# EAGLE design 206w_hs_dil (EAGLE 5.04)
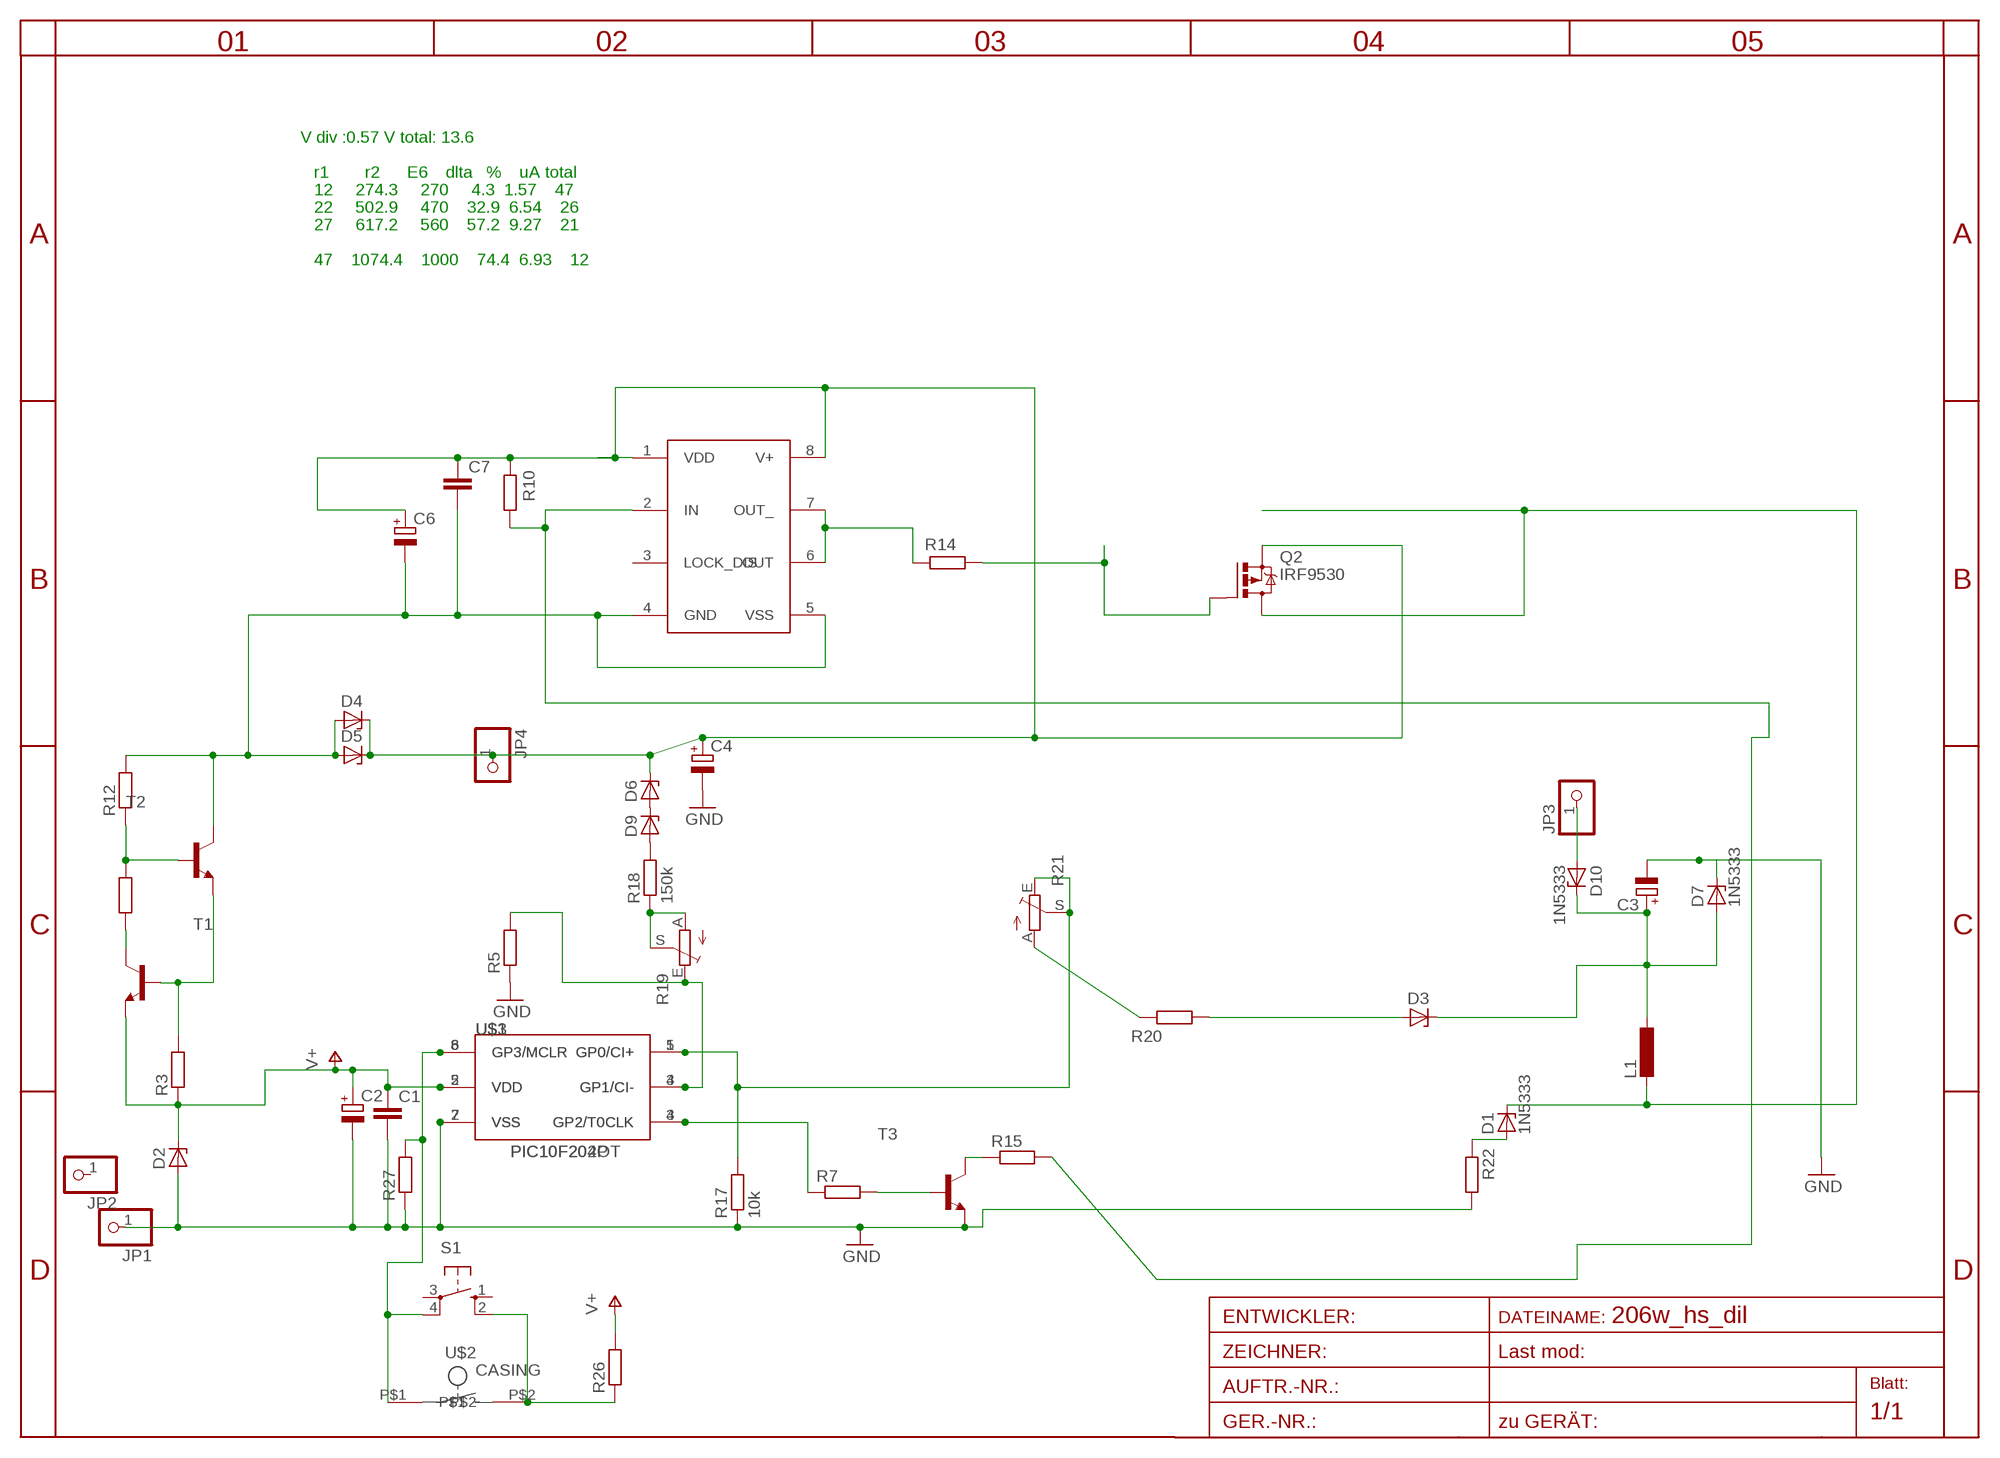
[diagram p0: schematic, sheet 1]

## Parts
C1  C-EUC1206  [C1206]
C2  CPOL-EUSANYO_SMD_E12  [SANYO-OSCON_SMD_E12]
C3  CPOL-EUE5-8.5  [E5-8,5]
C4  CPOL-EUE5-8.5  [E5-8,5]
C6  CPOL-EUSANYO_SMD_E12  [SANYO-OSCON_SMD_E12]
C7  C-EUC1206  [C1206]
D1  1N5333  [C1702-15]
D2  ZENER-DIODESOT23  [SOT23]
D3  ZENER-DIODESMB  [SMB]
D4  ZENER-DIODESMB  [SMB]
D5  ZENER-DIODESMB  [SMB]
D6  ZENER-DIODESMB  [SMB]
D7  1N5333  [C1702-15]
D9  ZENER-DIODESMB  [SMB]
D10  1N5333  [C1702-15]
IC3  TC4432X  [SO-08]
JP1  PINHD-1X1  [1X01]
JP2  PINHD-1X1  [1X01]
JP3  PINHD-1X1  [1X01]
JP4  PINHD-1X1  [1X01]
L1  L-EU2200-15.24  [2200-15.24]
Q2  IRF9530  [TO220BV]
R3  R-EU_R0805  [R0805]
R5  R-EU_R0805  [R0805]
R7  R-EU_R0805  [R0805]
R10  R-EU_R0805  [R0805]
R12  R-EU_R0805  [R0805]
R14  R-EU_0204/2V  [0204V]
R15  R-EU_R0805  [R0805]
R17  10k  R-EU_R0805  [R0805]
R18  150k  R-EU_R1206  [R1206]
R19  TRIM_EU-CA6V  [CA6V]
R20  R-EU_R0805  [R0805]
R21  TRIM_EU-CA6V  [CA6V]
R22  R-EU_0309/12  [0309/12]
R24  R-EU_R1206  [R1206]
R26  R-EU_R0805  [R0805]
R27  R-EU_R0805  [R0805]
S1  10-XX  [B3F-10XX]
T1  BC846BLT1-NPN-SOT23-BEC  [SOT23-BEC]
T2  BC846BLT1-NPN-SOT23-BEC  [SOT23-BEC]
T3  BC846BLT1-NPN-SOT23-BEC  [SOT23-BEC]
U$1  PIC10F202OT  [SOT23-6]
U$2  CASING  [CASING]
U$3  PIC10F204P  [DIL8]

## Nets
BB: IC3.2(IN) R10.1 R15.2
EXIT: D10.A JP3.1
GND: C1.2 C2.- C3.- C4.- D2.1(A) D7.C JP1.1 R5.1 R17.1 R22.2 R27.1 T3.E U$1.2(VSS) U$3.7(VSS)
HOTSPOT: D1.C L1.2 Q2.D
N$1: D3.A R20.2
N$2: R15.1 T3.C
N$3: R5.2 R19.E U$1.3(GP1/CI-) U$3.4(GP1/CI-)
N$4: D9.A R18.2
N$5: R7.2 T3.B
N$6: C6.- C7.2 D4.A D5.A IC3.4(GND) IC3.5(VSS) R12.2 T2.C
N$7: R27.2 S1.4(P1) U$1.6(GP3/MCLR) U$2.P$1 U$3.8(GP3/MCLR)
N$8: D1.A R22.1
N$9: R7.1 U$1.4(GP2/T0CLK) U$3.3(GP2/T0CLK)
N$10: Q2.G R14.1
N$11: IC3.6(OUT) IC3.7(OUT_) R14.2
N$12: R3.2 T1.B T2.E
N$13: R18.1 R19.A R19.S
N$14: R17.2 R21.E R21.S U$1.1(GP0/CI+) U$3.5(GP0/CI+)
N$17: R26.1 S1.2(S1) U$2.P$2
N$19: R24.1 T1.C
N$22: R12.1 R24.2 T2.B
N$23: D6.A D9.C
N$25: R20.1 R21.A
V60: C4.+ C6.+ C7.1 D4.C D5.C D6.C IC3.1(VDD) IC3.8(V+) JP4.1 Q2.S R10.2
V+: C1.1 C2.+ D2.3(C) R3.1 R26.2 T1.E U$1.5(VDD) U$3.2(VDD)
VOUT: C3.+ D3.C D7.A D10.C L1.1
Unconnected: IC3.3(LOCK_DIS) JP2.1 S1.1(S) S1.3(P)

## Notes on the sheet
- V div :0.57 V total: 13.6
- r1        r2      E6    dlta   %    uA total
- 12     274.3     270     4.3  1.57    47
- 22     502.9     470    32.9  6.54    26
- 27     617.2     560    57.2  9.27    21
- 47    1074.4    1000    74.4  6.93    12

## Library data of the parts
C1 C7 = rcl:C-EU: CAPACITOR, European symbol
C2-C4 C6 = rcl:CPOL-EU: POLARIZED CAPACITOR, European symbol
D1 D7 D10 = diode-1:1N5333: Z DIODE
D2-D6 D9 = diode-1:ZENER-DIODE: Z-Diode
IC3 = microchip:TC4432
JP1-JP4 = pinhead:PINHD-1X1: PIN HEADER
L1 = rcl:L-EU: INDUCTOR, European symbol
Q2 = transistor-power:IRF9530: P-CHANNEL HEXFET POWER-MOS-FET Source: http://www.irf.com/product-info/datasheets/data/irf9530.pdf
R3 R5 R10 R12 R14 R15 R20 R24 R26 R27 = rcl:R-EU_: RESISTOR, European symbol
R7 R17 R18 R22 = rcl-2:R-EU_: RESISTOR, European symbol
R19 R21 = pot:TRIM_EU-: POTENTIOMETER
S1 = switch-omron:10-XX: OMRON SWITCH
T1-T3 = transistor-neu-to92:*-NPN-: NPN Transistror
U$1 U$3 = microchip-5:PIC10F2*: uPC nW 0,25/0,5k Program Flash memory Comparator
U$2 = button:CASING

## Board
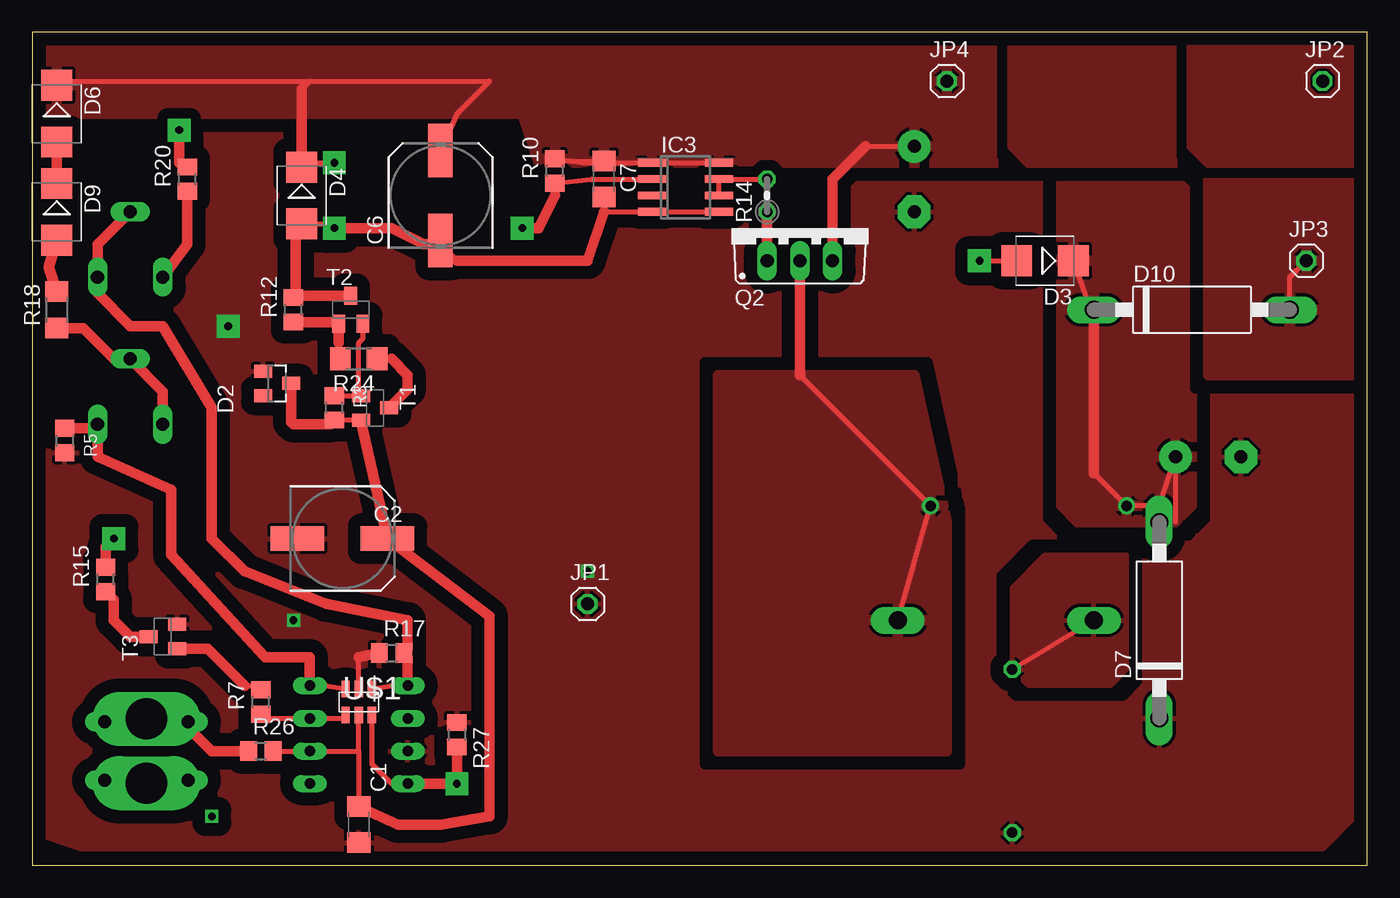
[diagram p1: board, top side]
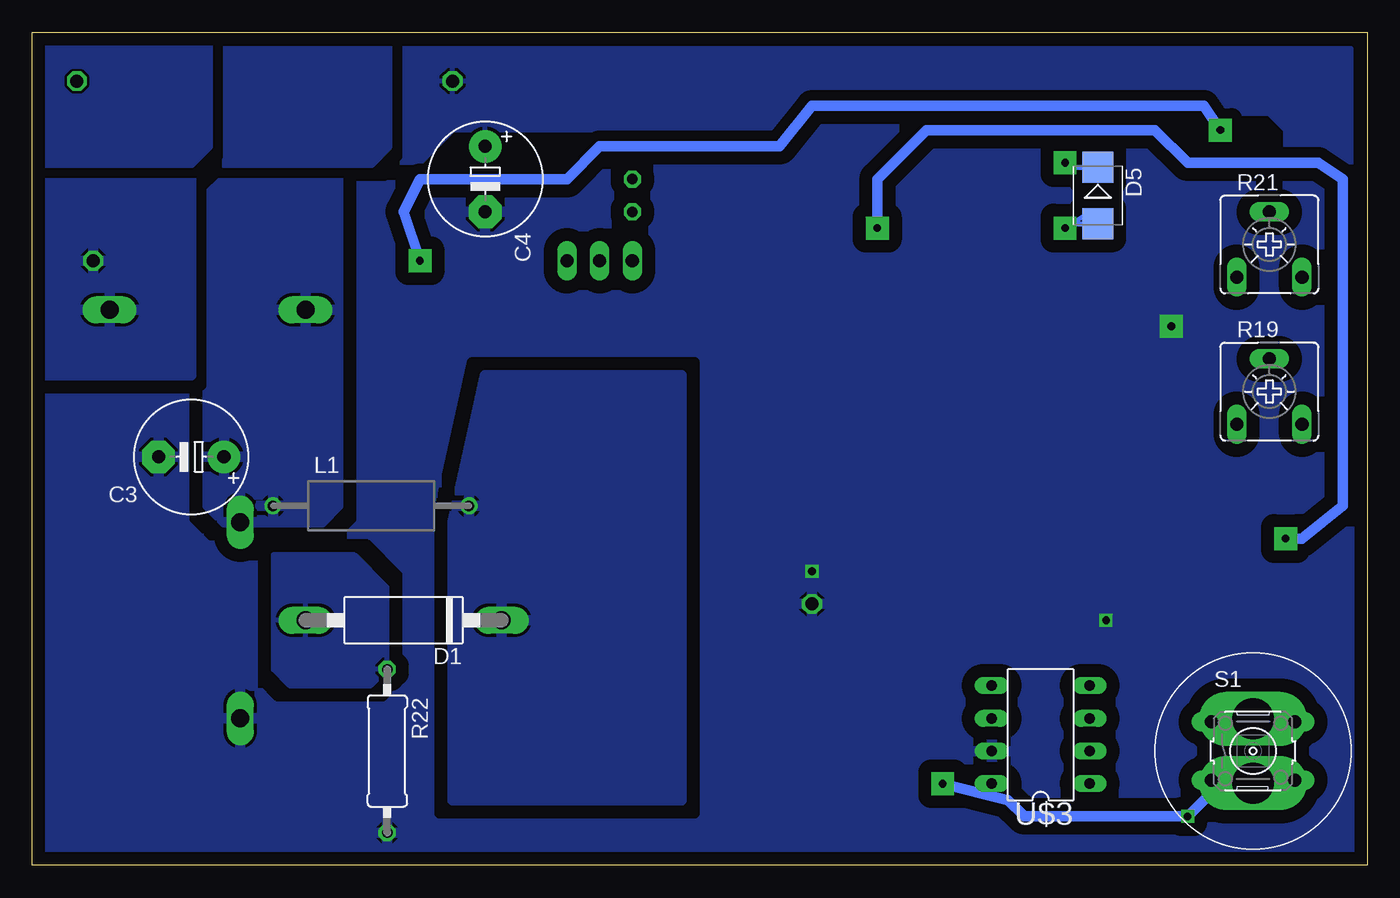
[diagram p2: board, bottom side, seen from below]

Size 103.81 x 64.76 mm. Coordinates in mm from the lower left corner, seen from the top.
Outline: 0,0 103.81,0 103.81,64.76 0,64.76 0,0
Copper layers (1*16): Top 0.035mm / dielectric 1.5mm / Bottom 0.035mm
Design rules "default": minimum track width 10mil, minimum drill 24mil, track to track 8mil, track to pad 8mil, pad to pad 8mil, via to via 8mil, smd to smd 8mil, copper to edge 40mil, drill to drill 8mil, minimum pad ring 10mil, minimum via ring 8mil, stop-mask expansion 4mil, vias tented up to drill 0mil, thermal gap 10mil

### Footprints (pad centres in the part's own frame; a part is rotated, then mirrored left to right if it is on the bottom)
C1206 = smd 1.6 x 1.8: 1 -1.4,0; 2 1.4,0
SANYO-OSCON_SMD_E12 = smd 4.15 x 1.9: + 3.5,0; - -3.5,0
E5-8,5 = drill 1.016 pad 2.54 round: + -2.54,0 | drill 1.016 pad 2.54 octagon: - 2.54,0
C1702-15 = drill 1.397 long: A 7.62,0; C -7.62,0
SOT23 = smd 1 x 1.4: 1 -0.95,-1.1; 2 0.95,-1.1; 3 0,1.1
SMB = smd 2.4 x 2.4: A 2.2,0; C -2.2,0
SO-08 = smd 0.6 x 2.2: 1 -1.905,-2.6; 2 -0.635,-2.6; 3 0.635,-2.6; 4 1.905,-2.6; 5 1.905,2.6; 6 0.635,2.6; 7 -0.635,2.6; 8 -1.905,2.6
1X01 = drill 1.016 octagon: 1 0,0
2200-15.24 = drill 0.8 pad 1.27 round: 1 -7.62,0; 2 7.62,0
TO220BV = drill 1.016 long: D 0,-2.54; G -2.54,-2.54; S 2.54,-2.54
R0805 = smd 1.3 x 1.5: 1 -0.95,0; 2 0.95,0
0204V = drill 0.813 octagon: 1 -1.27,0; 2 1.27,0
R1206 = smd 1.6 x 1.803: 1 -1.422,0; 2 1.422,0
CA6V = drill 1.016 long: A -2.54,-2.54; E 2.54,-2.54; S 0,2.54
0309/12 = drill 0.813 octagon: 1 -6.35,0; 2 6.35,0
B3F-10XX = drill 1.016 long: 1 -3.251,2.261; 2 3.251,2.261; 3 -3.251,-2.261; 4 3.251,-2.261
SOT23-BEC = smd 1 x 1.4: B -0.95,-1.1; C 0,1.1; E 0.95,-1.1
SOT23-6 = smd 0.635 x 1.27: 1 -1.016,-1.016; 2 0,-1.016; 3 1.016,-1.016; 4 1.016,1.016; 5 0,1.016; 6 -1.016,1.016
CASING = drill 3.2 pad 3.81 long: P$1 -2.5,0; P$2 2.5,0
DIL8 = drill 0.813 long: 1 -3.81,-3.81; 2 -1.27,-3.81; 3 1.27,-3.81; 4 3.81,-3.81; 5 3.81,3.81; 6 1.27,3.81; 7 -1.27,3.81; 8 -3.81,3.81

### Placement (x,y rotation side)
C1  25.4,3.17 270 top
C2  24.13,25.4 0 top
C3  91.44,31.75 180 bottom
C4  68.58,53.34 270 bottom
C6  31.75,52.07 90 top
C7  44.45,53.34 270 top
D1  74.93,19.05 180 bottom
D2  19.05,37.47 270 top
D3  78.74,46.99 180 top
D4  20.95,52.07 270 top
D5  20.95,52.07 270 bottom
D6  1.91,58.42 270 top
D7  87.63,19.05 90 top
D9  1.91,50.8 270 top
D10  90.17,43.18 0 top
IC3  50.8,52.7 270 top
JP1  43.18,20.32 0 top
JP2  100.33,60.96 0 top
JP3  99.06,46.99 0 top
JP4  71.12,60.96 0 top
L1  77.47,27.94 0 bottom
Q2  59.69,49.53 0 top
R3  23.5,35.56 90 top
R5  2.54,33.02 90 top
R7  17.78,12.7 90 top
R10  40.64,53.98 90 top
R12  20.32,43.18 90 top
R14  57.15,52.07 90 top
R15  5.71,22.23 90 top
R17  27.94,16.51 0 top
R18  1.91,43.18 90 top
R19  7.62,36.83 0 bottom
R20  12.06,53.34 90 top
R21  7.62,48.26 0 bottom
R22  76.2,8.89 270 bottom
R24  25.4,39.37 180 top
R26  17.78,8.89 0 top
R27  33.02,10.16 270 top
S1  8.89,8.89 0 bottom
T1  26.67,35.56 270 top
T2  24.77,43.18 0 top
T3  10.16,17.78 90 top
U$1  25.4,12.7 180 top
U$2  8.89,8.89 90 bottom
U$3  25.4,10.16 90 bottom

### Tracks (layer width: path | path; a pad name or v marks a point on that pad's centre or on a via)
BB  (via drill 0.6 pad 1.78)
  Top 0.406: IC3.2 43.5,53.34 R10.1 40.64,52.07 | 5.71,24.77 v6.35,25.4
  Top 0.813: 40.64,52.07 39.37,49.53 v38.1,49.53 | R15.2 5.71,24.77
  Bottom 0.813: v6.35,25.4 5.08,25.4 1.91,27.94 1.91,53.34 3.81,54.61 13.97,54.61 16.51,57.15 34.29,57.15 38.1,53.34 v38.1,49.53
EXIT
  Top 0.406: D10.A 97.79,45.72 JP3.1
  pour Top (isolate 0.813, rank 2): 91.44,53.34 102.87,53.34 102.87,38.1 91.44,38.1
  pour Bottom (isolate 0.813, rank 2): 91.44,53.34 102.87,53.34 102.87,38.1 91.44,38.1
GND  (via drill 0.6, 0.6 pad 1.78)
  Top 0.406: U$1.2 25.4,16.19
  Top 0.813: 25.4,16.19 R17.1
  other vias: 15.24,41.91 20.32,19.05 43.18,22.86
  pour Bottom (isolate 1.016, rank 5): 102.87,60.96 102.87,0 90.17,0 1.27,1.27 1.27,53.34 1.27,58.42
  pour Top (isolate 1.016, rank 5): 0,63.5 99.06,63.5 102.87,59.69 102.87,3.81 100.33,1.27 3.81,1.27 0,2.54
HOTSPOT
  Top 0.406: 59.69,38.1 L1.2 D1.C
  Top 0.813: 59.69,38.1 Q2.D
  pour Top (isolate 0.813, rank 3): 53.34,38.1 68.58,38.1 71.12,26.67 71.12,8.89 53.34,8.89
  pour Bottom (isolate 0.813, rank 3): 53.34,38.1 68.58,38.1 71.12,26.67 71.12,5.08 53.34,5.08
N$1  (via drill 0.6 pad 1.78)
  Top 0.406: v73.66,46.99 D3.A | 11.43,54.61 11.74,54.61 R20.2
  Top 0.813: 11.43,54.61 v11.43,57.15
  Bottom 0.813: v73.66,46.99 74.93,50.8 73.66,53.34 62.23,53.34 59.69,55.88 45.72,55.88 43.18,59.05 12.7,59.05 v11.43,57.15
N$2
  Top 0.406: 6.35,20.64 R15.1
  Top 0.813: T3.C 7.62,17.78 6.35,19.05 6.35,20.64
N$3
  Top 0.406: U$1.3 22.86,13.97 U$3.4 | R19.E 4.76,33.97
  Top 0.813: U$3.4 21.59,16.19 18.1,16.19 10.79,24.13 10.79,29.21 5.08,31.75 R19.E | 4.76,33.97 R5.2
N$4
  Top 0.813: D9.A 1.27,46.51 R18.2
N$5
  Top 0.406: 16.51,13.97 17.46,13.97 R7.2
  Top 0.813: T3.B 13.65,16.83 16.51,13.97
N$6  (via drill 0.6 pad 1.78)
  Top 0.406: C7.2 44.45,50.8 IC3.4 IC3.5 | R12.2 20.47,44.28 | 20.47,49.38 D5.A 23.2,49.87 v23.5,49.53 | 33.02,46.99 31.75,48.26 C6.-
  Top 0.813: T2.C 20.47,44.28 20.47,49.38 | 33.02,46.99 43.18,46.99 44.45,50.8 | v23.5,49.53 27.94,49.53 30.48,48.26 31.75,48.26
  Bottom 0.406: 20.32,49.53 21.59,50.8 v23.5,49.53 23.2,49.87 D5.A
N$7  (via drill 0.6, 0.6 pad 1.78)
  Top 0.406: U$1.6 26.42,7.87 27.94,6.35 U$3.8
  Top 0.813: U$3.8 v33.02,6.35 R27.2
  Bottom 0.406: S1.4 11.15,6.63 11.43,6.35 11.39,6.39 U$2.P$1
  Bottom 0.813: v33.02,6.35 27.94,5.08 26.67,3.81 v13.97,3.81 11.43,6.35
N$8
  Top 0.406: R22.1 D1.A
  pour Top (isolate 0.813): 76.2,15.24 76.2,21.59 78.74,24.13 85.09,24.13 85.09,15.24 83.82,13.97 77.47,13.97
  pour Bottom (isolate 0.813): 76.2,15.24 76.2,21.59 78.74,24.13 85.09,24.13 85.09,15.24 83.82,13.97 77.47,13.97
N$9
  Top 0.406: R7.1 18.1,11.43 U$3.3 24.13,11.43 U$1.4
N$10
  Top 0.813: Q2.G R14.1
N$11
  Top 0.406: R14.2 IC3.7 IC3.6
N$12
  Top 0.406: T2.E 25.71,40.95 25.4,40.64 25.4,36.68 T1.B R3.2
N$13
  Top 0.406: 6.35,39.37 R19.S
  Top 0.813: R18.1 3.96,41.76 6.35,39.37 | R19.S 10.16,36.83 R19.A
N$14
  Top 0.406: 29.21,16.19 R17.2 29.21,16.83 | U$1.1 27.94,13.97 U$3.5 | 5.08,44.45 R21.E
  Top 0.813: U$3.5 29.21,16.19 | R21.E 5.08,48.26 R21.S | 5.08,44.45 7.62,41.91 10.16,41.91 13.97,35.56 13.97,25.4 16.51,22.86 22.86,20.32 29.21,19.05 29.21,16.83
N$15
  pour Top: 90.17,64.77 90.17,55.88 91.44,54.61 102.87,54.61 102.87,63.5 101.6,64.77
  pour Bottom: 90.17,64.77 90.17,55.88 91.44,54.61 102.87,54.61 102.87,63.5 101.6,64.77
N$16
  pour Top (isolate 0.813, rank 2): 76.2,63.5 76.2,55.88 77.47,54.61 88.9,54.61 90.17,55.88 90.17,62.23 88.9,63.5
  pour Bottom (isolate 0.813, rank 2): 76.2,63.5 76.2,55.88 77.47,54.61 88.9,54.61 90.17,55.88 90.17,62.23 88.9,63.5
N$17
  Top 0.406: 11.43,11.43 8.93,11.43 U$2.P$2 8.65,11.15 S1.2
  Top 0.813: R26.1 13.97,8.89 11.43,11.43
N$19
  Top 0.406: 27.94,39.37 R24.1
  Top 0.813: 27.94,39.37 29.21,38.1 29.21,37 T1.C
N$22
  Top 0.406: 23.66,42.23 T2.B | 23.82,40.64 R24.2
  Top 0.813: R12.1 23.66,42.23 | T2.B 23.82,40.64
N$23
  Top 0.813: D9.C D6.A
N$25
  Top 0.406: 12.06,51.76 R20.1
  Top 0.813: R21.A 12.06,48.26 12.06,51.76
V60  (via drill 0.6 pad 1.78)
  Top 0.406: IC3.8 IC3.1 42.87,54.61 R10.2 | C7.1 41.91,54.74 R10.2 | 40.02,54.92 R10.2 | 21.59,60.96 2.54,60.96 D6.C | 21.59,60.96 35.56,60.96 33.02,58.42 C6.+ | 64.77,55.88 C4.+ | 21.59,60.96 20.95,60.33 | v23.5,54.61 21.3,54.61 D5.C
  Top 0.813: Q2.S 62.23,53.34 64.77,55.88 | 20.95,60.33 D5.C
  Bottom 0.406: D5.C 23.16,54.27 v23.5,54.61
  pour Top (isolate 0.813, rank 4): 102.87,63.5 1.27,63.5 1.27,58.42 38.1,58.42 39.37,54.61 100.33,54.61 101.6,55.88
  pour Bottom (isolate 0.813, rank 4): 102.87,63.5 1.27,63.5 1.27,48.26 7.62,48.26 7.62,54.61 6.35,55.88 6.35,57.15 7.62,58.42 44.45,58.42 45.72,57.15 71.12,57.15 73.66,54.61 100.33,54.61 101.6,55.88
V+
  Top 0.406: 25.4,8.89 U$3.2 R26.2 | 25.4,8.89 U$1.5 | 25.4,8.89 C1.1 | 20.32,34.29 20.15,34.46 | 23.18,34.29 R3.1 T1.E 25.57,34.43
  Top 0.813: 20.15,34.46 D2.3 | 23.18,34.29 20.32,34.29 | 25.57,34.43 C2.+ 35.56,19.36 35.56,3.81 31.75,3.17 28.45,3.17 C1.1
VOUT
  Top 0.406: D3.C 82.21,43.52 D10.C | 82.55,30.48 L1.1 87.63,27.94 | 87.63,27.94 C3.+ 88.9,26.67 87.63,27.94 | D7.A 87.63,27.94
  Top 0.813: 82.55,30.48 D10.C
  pour Top (isolate 1.016, rank 3): 80.01,53.34 80.01,27.94 81.28,26.67 88.9,26.67 90.17,27.94 90.17,52.07 88.9,53.34
  pour Bottom (isolate 0.813, rank 3): 80.01,53.34 80.01,27.94 81.28,26.67 88.9,26.67 90.17,27.94 90.17,52.07 88.9,53.34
